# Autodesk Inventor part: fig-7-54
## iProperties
Shininess: 77.0
Length Units: 11269
Angle Units: 11279
Time Units: 11290
Mass Units: 11283
Length Display Precision: 3
Angle Display Precision: 2
Created: 2002-01
Part Number: fig-7-54
Document SubType Name: Modeling
Designer: ***
Density: 1 g/cm^3
Density: 0.0
Volumn: 0.0
Area: 0.0
PropertySet Name: Model Information
Control State: 0
Master: False
Checked Out: False
Author: ***
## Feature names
1. Extrusion1
2. Split5
